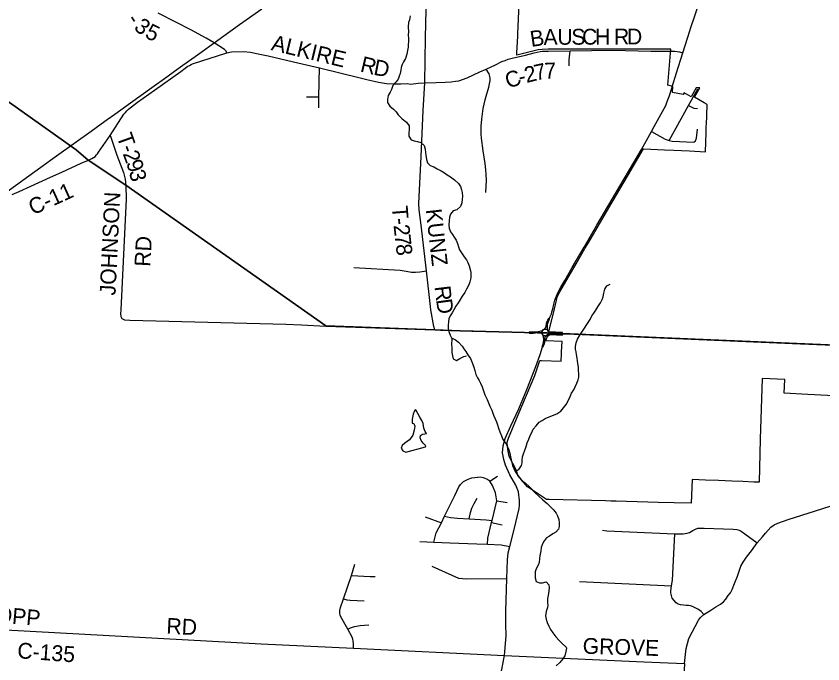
# Model space of a CAD drawing. Extents: x 114604 to 551442, y 316898 to 567001.
# Drawn here: x 152694 to 167961, y 354850 to 367117 of the extents above; entities that cross this region are included whole.
import ezdxf

# ---------------------------------------------------------------- set-up
doc = ezdxf.new("R2010")
doc.units = 0
for name, color, linetype in [('GE_P_Alignment_1000_Bearings', 7, 'Continuous'), ('GE_P_Alignment_1000_Cardinal_Points', 7, 'Continuous'), ('GE_P_Alignment_100_Stations', 7, 'Continuous'), ('GE_P_Alignment_500_Bearings', 7, 'Continuous'), ('GE_P_Alignment_500_Distances', 7, 'Continuous'), ('MT_X_Edge_Line', 7, 'Continuous'), ('PM_P_Cells', 7, 'Continuous'), ('PM_P_CL_Double_Solid', 7, 'Continuous'), ('PM_P_Crosswalk', 7, 'Continuous')]:
    doc.layers.add(name, color=color, linetype=linetype)

msp = doc.modelspace()

# ---------------------------------------------------------------- linework, layer by layer
at = {"layer": 'GE_P_Alignment_1000_Bearings'}
msp.add_lwpolyline([(152238, 363592), (152931, 364091), (153164, 364258), (153458, 364468), (154115, 364941), (154304, 365077), (154417, 365157), (154560, 365260), (154858, 365474), (155261, 365764), (155545, 365968), (155690, 366072), (155851, 366188), (156081, 366353), (156217, 366450), (156352, 366546), (156441, 366612), (156924, 366959), (157342, 367257)], dxfattribs=at)
at = {"layer": 'GE_P_Alignment_1000_Cardinal_Points'}
for p, q in [((163160, 366178), (163161, 366271)), ((158188, 365591), (158422, 365588)), ((160617, 361174), (160725, 361170)), ((161317, 361151), (162394, 361123)), ((163004, 361103), (163057, 361101)), ((163057, 361101), (163110, 361098)), ((163110, 361098), (167387, 360918)), ((161658, 358308), (161802, 358406)), ((161792, 357935), (161985, 357904)), ((160433, 357638), (160743, 357522)), ((161691, 357527), (161890, 357483)), ((163358, 356409), (165099, 356328))]:
    msp.add_line(p, q, dxfattribs=at)
for points in [[(163161, 366271), (163161, 366290), (163180, 366460)], [(158424, 365378), (158422, 365588), (158436, 366135)], [(161590, 365599), (161638, 365772), (161665, 365898), (161666, 365949), (161643, 366023), (161588, 366115)], [(160617, 361174), (160596, 361238), (160543, 361555), (160535, 361619), (160457, 362293), (160361, 363160), (160324, 363451), (160318, 363567), (160359, 364461), (160400, 365332), (160431, 365854)], [(165050, 364762), (165420, 365427), (165594, 365741)], [(161584, 363777), (161594, 364008), (161590, 364118), (161582, 364208), (161571, 364327), (161534, 364564), (161501, 364806), (161496, 364881), (161492, 365036), (161505, 365168), (161530, 365365), (161571, 365531), (161590, 365599)], [(165420, 365427), (165521, 365374), (165592, 365368)], [(164719, 364933), (164979, 364787), (165050, 364762), (165110, 364750), (165517, 364729), (165553, 364757), (165572, 364807), (165586, 364976)], [(154474, 364859), (154489, 364827), (154602, 364486), (154724, 364154), (154755, 364030), (154770, 363911)], [(154770, 363911), (154778, 363650), (154673, 361553), (154669, 361481), (154673, 361427), (154697, 361391), (154745, 361367), (154847, 361357), (157801, 361281), (158095, 361268)], [(159085, 362354), (159959, 362309), (160073, 362288), (160177, 362269), (160251, 362266), (160331, 362277), (160457, 362293)], [(158095, 361268), (158557, 361248), (160617, 361174)], [(160725, 361170), (161096, 361157), (161317, 361151)], [(162394, 361123), (162411, 361136), (162438, 361136), (162476, 361138), (162529, 361141), (162573, 361144), (162608, 361149), (162633, 361157), (162650, 361165), (162674, 361180)], [(162394, 361123), (162410, 361112), (162440, 361112), (162478, 361115), (162525, 361120), (162574, 361125), (162601, 361125), (162624, 361117), (162642, 361106), (162649, 361099)], [(162649, 361099), (162659, 361086), (162671, 361077), (162683, 361071), (162695, 361067), (162708, 361065), (162720, 361068), (162734, 361075)], [(162674, 361180), (162687, 361186), (162700, 361190), (162714, 361190), (162731, 361186), (162747, 361177), (162753, 361171), (162759, 361161)], [(162734, 361075), (162755, 361083), (162777, 361091), (162809, 361097), (162843, 361099), (162877, 361098), (162984, 361093), (163004, 361103)], [(162759, 361161), (162770, 361147), (162781, 361135), (162794, 361127), (162809, 361121), (162826, 361119), (162862, 361118), (162940, 361117), (162968, 361115), (162986, 361113), (163004, 361103)], [(167387, 360918), (169394, 360833), (170478, 360795)], [(160602, 357152), (160630, 357282), (160646, 357332), (160743, 357522), (160802, 357648), (160999, 358038), (161074, 358204), (161104, 358246), (161162, 358303), (161250, 358347), (161318, 358375), (161430, 358389)], [(161612, 357116), (161620, 357230), (161691, 357527), (161705, 357565), (161792, 357935), (161768, 358090), (161710, 358228), (161658, 358308), (161602, 358348), (161538, 358374), (161506, 358380), (161430, 358389)], [(161265, 357594), (161291, 357720), (161319, 357802), (161363, 357887), (161417, 357987)], [(160802, 357648), (160913, 357623), (161045, 357607), (161265, 357594), (161589, 357577), (161705, 357565)], [(163791, 357381), (163873, 357371), (165163, 357313), (165315, 357311), (165396, 357323), (165437, 357339), (165498, 357376), (165549, 357404), (165597, 357418), (165646, 357423), (165717, 357422), (166267, 357400), (166331, 357393), (166375, 357382), (166416, 357364), (166486, 357315), (166718, 357144)], [(165707, 355785), (165657, 355839), (165606, 355878), (165497, 355935), (165459, 355950), (165421, 355955), (165375, 355957), (165321, 355959), (165270, 355966), (165225, 355981), (165185, 356007), (165145, 356049), (165112, 356096), (165095, 356145), (165085, 356193), (165086, 356236), (165099, 356328), (165113, 356433), (165163, 357313)], [(160334, 357167), (160602, 357152), (160904, 357142), (161414, 357122), (161612, 357116), (161872, 357105), (162036, 357070)], [(159078, 355148), (159079, 355238), (159073, 355282), (159064, 355321), (159052, 355353), (158973, 355507), (158839, 355741), (158829, 355770), (158823, 355810), (158823, 355861), (158830, 355916), (158888, 356083), (159038, 356524), (159103, 356737)], [(160559, 356701), (161065, 356474), (161219, 356461), (161979, 356467)], [(159038, 356524), (159394, 356505), (159491, 356504)], [(158888, 356083), (158954, 356065), (159018, 356057), (159282, 356047)], [(158973, 355507), (159024, 355532), (159099, 355560), (159207, 355576), (159367, 355587)]]:
    msp.add_lwpolyline(points, dxfattribs=at)
at = {"layer": 'GE_P_Alignment_100_Stations'}
msp.add_lwpolyline([(168540, 359910), (167678, 359953), (167227, 359975), (167239, 360236), (166810, 360257), (166777, 359104), (166754, 358290), (166655, 358294), (166448, 358302), (166239, 358310), (165989, 358320), (165740, 358330), (165490, 358340), (165469, 357891), (165149, 357900), (164847, 357908), (164647, 357914), (164447, 357919), (164248, 357925), (164048, 357930), (163951, 357932), (163847, 357935), (162780, 357963), (162731, 357964), (162374, 358204), (162295, 358293), (162186, 358418), (162163, 358511), (162024, 358779), (162002, 358919), (161984, 359031), (161992, 359069), (162011, 359127), (162198, 359569), (162508, 360309), (162606, 360595), (162637, 360594), (163010, 360582), (163011, 360612), (163014, 360687), (163017, 360762), (163025, 360955), (162719, 360967), (162751, 361058), (162807, 361085), (163031, 361075), (163031, 361075), (163031, 361086), (163034, 361126), (162774, 361136), (162880, 361576), (162920, 361740), (162936, 361794), (162956, 361846), (162981, 361897), (163290, 362425), (163459, 362715), (163532, 362839), (163911, 363489), (164264, 364086), (164564, 364603), (164575, 364602), (164964, 364585), (165138, 364577), (165289, 364570), (165438, 364563), (165639, 364554), (165741, 364549), (165747, 364729), (165753, 364905), (165756, 364987), (165761, 365118), (165763, 365187), (165765, 365235), (165773, 365445), (165718, 365476), (165531, 365582), (165632, 365760), (165562, 365761), (165466, 365588), (165335, 365662), (165319, 365633), (165114, 365673), (165124, 365784), (165025, 365812), (165087, 366491), (164992, 366494), (163890, 366493), (162763, 366494), (162646, 366486), (162576, 366476), (162171, 366378), (162179, 366571), (162180, 366588), (162188, 366780), (162230, 367784)], dxfattribs=at)
at = {"layer": 'GE_P_Alignment_500_Bearings'}
msp.add_line((165345, 354855), (165285, 353903), dxfattribs=at)
for points in [[(160431, 365854), (160440, 366710), (160471, 368026), (160485, 368388), (160489, 368477), (160495, 368532), (161383, 368509), (162233, 368476), (162646, 368457), (163006, 368450), (163461, 368434), (163968, 368418), (164072, 368411), (164726, 368389), (164923, 368382)], [(165472, 366920), (165531, 367102), (165640, 367430), (165714, 367677), (165746, 367821), (165765, 367984), (165766, 368101), (165764, 368348)], [(156684, 366423), (156669, 366453), (156634, 366483), (156441, 366609), (156289, 366702), (156000, 366860), (155731, 366994), (155380, 367170)], [(165104, 365755), (165111, 365780), (165193, 366042), (165313, 366420), (165408, 366718), (165472, 366920)], [(156684, 366423), (156769, 366442), (156995, 366444), (157131, 366435), (157272, 366405), (157464, 366363), (157942, 366250), (158436, 366135), (159203, 365947), (159334, 365914), (159550, 365867), (159704, 365842), (159835, 365833), (159974, 365836), (160095, 365843), (160166, 365827), (160300, 365846), (160431, 365854)], [(160431, 365854), (160641, 365857), (160815, 365866), (160928, 365872), (161006, 365883), (161071, 365894), (161228, 365948), (161469, 366061), (161588, 366115), (161764, 366197), (161886, 366255), (161951, 366278), (162007, 366300), (162083, 366320), (162332, 366380), (162497, 366421), (162609, 366445), (162646, 366451), (162695, 366454), (162768, 366455), (163180, 366460), (163986, 366470), (164704, 366455), (165084, 366454), (165156, 366456), (165161, 366455)], [(165161, 366455), (165207, 366449), (165251, 366439), (165313, 366420)], [(154474, 364859), (154735, 365257), (154765, 365294), (154791, 365326), (154820, 365355), (154993, 365486), (155314, 365716), (155810, 366071), (155894, 366133), (155943, 366166), (155976, 366184), (156005, 366199), (156034, 366211), (156684, 366423)], [(164771, 365027), (164990, 365426), (165017, 365501), (165055, 365593), (165104, 365755)], [(162850, 361571), (162872, 361662), (162890, 361737), (162933, 361843), (162964, 361914), (163003, 361986), (163075, 362112), (163220, 362359), (163444, 362743), (163686, 363155), (164120, 363896), (164529, 364592), (164719, 364933), (164771, 365027)], [(154160, 364437), (154164, 364440), (154189, 364460), (154215, 364487), (154233, 364508), (154255, 364538), (154474, 364859)], [(152619, 363737), (152753, 363798), (152969, 363897), (153346, 364069), (153556, 364164), (153927, 364330), (154061, 364387), (154129, 364418), (154160, 364437)], [(162786, 361399), (162800, 361430), (162812, 361456), (162823, 361482), (162835, 361515), (162850, 361571)], [(162674, 361180), (162695, 361198), (162712, 361216), (162724, 361236), (162727, 361255), (162730, 361278), (162734, 361300), (162739, 361319), (162748, 361341), (162757, 361360), (162773, 361389), (162786, 361399)], [(162759, 361161), (162752, 361187), (162750, 361209), (162751, 361235), (162753, 361272), (162759, 361298), (162770, 361336), (162781, 361363), (162791, 361382), (162786, 361399)], [(162649, 361099), (162647, 361113), (162647, 361126), (162649, 361138), (162654, 361154), (162659, 361166), (162674, 361180)], [(162657, 360853), (162652, 360865), (162661, 360891), (162672, 360928), (162677, 360955), (162680, 360982), (162678, 361009), (162676, 361032), (162672, 361053), (162664, 361073), (162649, 361099)], [(162734, 361075), (162750, 361086), (162760, 361097), (162765, 361113)], [(162765, 361113), (162767, 361131), (162765, 361145), (162759, 361161)], [(162657, 360853), (162673, 360863), (162682, 360885), (162692, 360911), (162697, 360938), (162702, 360968), (162704, 360998), (162703, 361021), (162706, 361040), (162714, 361054), (162722, 361065), (162734, 361075)], [(161963, 355612), (161960, 355849), (161979, 356467), (161990, 356823), (162006, 356953), (162036, 357070), (162120, 357394), (162214, 357791), (162218, 357856), (162222, 357944), (162199, 358106), (162153, 358232), (162039, 358428), (161954, 358615), (161924, 358721), (161900, 358849), (161912, 358979), (161952, 359118), (162058, 359358), (162208, 359683), (162359, 360048), (162529, 360480), (162610, 360708), (162657, 360853)], [(165345, 354855), (165374, 355142), (165427, 355330), (165605, 355678), (165643, 355727), (165707, 355785), (165839, 355867), (165937, 355929), (166025, 355984), (166079, 356025), (166127, 356076), (166171, 356142), (166211, 356195), (166243, 356261), (166288, 356371), (166343, 356510), (166376, 356609), (166411, 356699), (166455, 356778), (166519, 356868), (166608, 356993), (166718, 357144), (166816, 357259), (166878, 357326), (166977, 357437), (167039, 357481), (167109, 357517), (167303, 357582), (168476, 357954)], [(161939, 355007), (161966, 355382), (161963, 355597), (161963, 355612)], [(151703, 355576), (151739, 355560), (151791, 355541), (152044, 355517), (152497, 355497), (157329, 355232), (159078, 355148), (161939, 355007)], [(160403, 351997), (160487, 352071), (160621, 352165), (160745, 352275), (160859, 352435), (160968, 352619), (161100, 352900), (161324, 353358), (161506, 353819), (161706, 354289), (161856, 354646), (161884, 354744), (161907, 354845), (161939, 355007)], [(161939, 355007), (164576, 354891), (165345, 354855)]]:
    msp.add_lwpolyline(points, dxfattribs=at)
at = {"layer": 'GE_P_Alignment_500_Distances'}
for points in [[(146990, 369445), (153829, 364582), (154060, 364390), (154769, 363914), (158556, 361251), (160616, 361177), (161095, 361159), (162560, 361122), (162739, 361117), (169393, 360836), (170477, 360798), (172520, 360708), (172368, 357901), (172150, 354165)], [(169393, 360836), (162739, 361117), (162560, 361122), (161095, 361159), (160616, 361177), (158556, 361251), (154769, 363914), (154060, 364390), (153829, 364582), (146990, 369445)]]:
    msp.add_lwpolyline(points, dxfattribs=at)
at = {"layer": 'MT_X_Edge_Line'}
for points in [[(160440, 358958), (160446, 358978), (160396, 359032), (160356, 359080), (160342, 359134), (160349, 359178), (160385, 359202), (160431, 359204), (160459, 359216), (160435, 359252), (160409, 359314), (160400, 359405), (160372, 359461), (160334, 359521), (160296, 359589), (160265, 359647), (160247, 359659), (160229, 359631), (160206, 359578), (160190, 359487), (160186, 359443), (160188, 359407), (160220, 359401), (160237, 359349), (160229, 359279), (160203, 359181), (160138, 359095), (160052, 359033), (160000, 358987), (159983, 358935), (160015, 358887), (160071, 358861)], [(160071, 358861), (160440, 358958)]]:
    msp.add_lwpolyline(points, dxfattribs=at)
at = {"layer": 'PM_P_Cells'}
for points in [[(160152, 367124), (160138, 367046), (160121, 366994), (160113, 366912), (160117, 366818), (160116, 366760), (160118, 366684), (160118, 366628), (160115, 366578), (160111, 366526), (160103, 366466), (160089, 366394), (160060, 366312), (160024, 366252), (159998, 366200), (159981, 366144), (159975, 366094), (159959, 366032), (159941, 365978), (159924, 365926), (159888, 365872), (159826, 365800), (159796, 365730), (159775, 365676), (159737, 365614), (159719, 365536), (159724, 365480), (159766, 365411), (159836, 365357), (159888, 365305), (159927, 365245), (159997, 365170), (160079, 365108), (160131, 365042), (160130, 364969), (160126, 364907)], [(160126, 364907), (160126, 364843), (160173, 364771), (160229, 364755), (160289, 364742), (160351, 364722), (160413, 364666), (160433, 364598), (160438, 364536), (160446, 364483), (160460, 364401), (160476, 364339), (160529, 364291), (160599, 364263), (160665, 364228), (160735, 364190), (160799, 364148), (160851, 364111), (160914, 364071), (160992, 364017), (161066, 363950), (161102, 363888), (161123, 363826), (161133, 363774), (161139, 363698), (161137, 363648), (161126, 363580), (161104, 363512), (161036, 363450), (160962, 363428), (160915, 363364), (160897, 363308), (160889, 363240), (160884, 363160), (160888, 363102), (160916, 363030), (160952, 362979), (160985, 362929), (161019, 362875), (161047, 362809), (161065, 362745), (161082, 362693), (161132, 362616), (161174, 362556), (161214, 362500), (161241, 362448), (161265, 362391), (161287, 362321), (161296, 362263), (161300, 362213), (161296, 362159), (161280, 362087), (161261, 362027), (161215, 361949), (161183, 361883), (161138, 361813), (161094, 361739), (161058, 361685), (161014, 361623), (160975, 361553), (160945, 361499), (160909, 361439), (160884, 361383), (160874, 361329), (160872, 361263), (160872, 361195), (160881, 361145), (160909, 361077), (160933, 361027), (161009, 360986), (161065, 360944), (161134, 360868), (161166, 360818), (161204, 360767), (161240, 360705), (161295, 360631), (161333, 360537), (161354, 360466), (161372, 360404), (161396, 360330), (161428, 360270), (161457, 360216), (161481, 360163), (161511, 360097), (161533, 360041), (161564, 359947), (161606, 359859), (161636, 359796), (161659, 359728), (161695, 359654), (161731, 359562), (161760, 359491), (161782, 359433), (161802, 359379), (161825, 359311), (161847, 359245), (161877, 359171), (161907, 359100), (161970, 359018), (161996, 358962), (162020, 358902)], [(162138, 358491), (162206, 358534), (162260, 358608), (162269, 358660), (162273, 358710), (162279, 358770), (162297, 358827), (162316, 358879), (162346, 358965), (162364, 359037), (162397, 359105), (162425, 359174), (162455, 359232), (162480, 359296), (162534, 359358), (162594, 359428), (162646, 359460), (162706, 359496), (162783, 359530), (162927, 359585), (163005, 359639), (163055, 359701), (163102, 359763), (163142, 359831), (163176, 359915), (163203, 359977), (163247, 360039), (163271, 360097), (163308, 360169), (163330, 360227), (163342, 360279), (163346, 360337), (163339, 360415), (163337, 360469), (163327, 360541), (163317, 360591), (163310, 360641), (163296, 360709), (163292, 360759), (163282, 360812), (163283, 360862), (163293, 360928), (163317, 361000), (163364, 361076), (163398, 361130), (163436, 361187), (163509, 361299), (163559, 361373), (163591, 361439), (163626, 361491), (163662, 361547), (163702, 361609), (163752, 361689), (163783, 361751), (163801, 361803), (163815, 361871), (163832, 361945), (163872, 362007), (163936, 362043)], [(160933, 361027), (160937, 361001), (160936, 360897), (160938, 360834), (160942, 360748), (160949, 360686), (160963, 360624), (161025, 360598), (161093, 360634), (161165, 360673), (161215, 360681)], [(162020, 358902), (162035, 358842), (162051, 358771), (162063, 358715), (162073, 358661), (162086, 358609), (162110, 358553), (162138, 358491), (162174, 358434), (162213, 358384), (162259, 358330), (162335, 358270), (162403, 358207), (162518, 358091), (162586, 358024), (162660, 357958), (162741, 357890), (162811, 357821), (162863, 357769), (162911, 357707), (162940, 357652), (162962, 357586), (162972, 357520), (162971, 357452), (162961, 357400), (162909, 357342), (162851, 357310), (162785, 357266), (162728, 357235), (162676, 357163), (162648, 357105), (162632, 357053), (162621, 356991), (162605, 356899), (162599, 356847), (162592, 356773), (162576, 356721), (162536, 356647), (162519, 356591), (162517, 356534), (162517, 356482), (162533, 356412), (162599, 356386), (162653, 356388), (162725, 356402), (162776, 356349), (162784, 356297), (162776, 356225), (162762, 356147), (162753, 356089), (162753, 356009), (162755, 355953), (162746, 355897), (162726, 355845), (162710, 355759), (162724, 355695), (162745, 355632), (162775, 355562), (162807, 355504), (162852, 355440), (162908, 355363), (162974, 355293), (163028, 355237), (163103, 355168)], [(163103, 355168), (163110, 355145), (163099, 355083), (163075, 355005), (163038, 354943), (162982, 354874), (162915, 354816)]]:
    msp.add_lwpolyline(points, dxfattribs=at)

# ---------------------------------------------------------------- texts
at = {"layer": 'PM_P_CL_Double_Solid'}
for s, rotation, p in [('-', 304.2729, (154774, 367048)), ('3', 320.4981, (154906, 366878)), ('5', 334.1524, (155114, 366719)), ('ALKIRE', 346.422, (157505, 366476)), ('B', 8.2941, (162442, 366533)), ('A', 1.3304, (162676, 366568)), ('U', 0.2958, (162938, 366574)), ('S', 0.2746, (163202, 366575)), ('C', 0.2719, (163405, 366576)), ('H', 0.2704, (163651, 366578)), ('R', 0.2719, (164008, 366579)), ('D', 0.2704, (164254, 366580)), ('R', 346.5228, (159190, 366070)), ('D', 349.1468, (159444, 366009)), ('2', 13.9324, (162352, 365849)), ('7', 12.3214, (162530, 365893)), ('7', 2.4164, (162697, 365931)), ('C', 18.8214, (162006, 365741)), ('-', 14.0927, (162233, 365819)), ('C-11', 24.3749, (153012, 363343)), ('KROPP', 355.1012, (151742, 355686)), ('RD', 356.959, (155531, 355423)), ('GROVE', 358.2168, (163412, 355044)), ('C-135', 355.7177, (152708, 354959))]:
    msp.add_text(s, height=300, rotation=rotation, dxfattribs=at).set_placement(p)
at = {"layer": 'PM_P_Crosswalk'}
for s, rotation, p in [('T', 289.6755, (154591, 364841)), ('-', 289.8544, (154666, 364629)), ('2', 290.0232, (154708, 364513)), ('9', 289.0862, (154771, 364342)), ('3', 282.6514, (154828, 364177)), ('JOHNSON', 87.2491, (154573, 361822)), ('T', 274.3453, (159803, 363515)), ('KUNZ', 276.37, (160446, 363454)), ('-', 276.1291, (159821, 363282)), ('2', 276.4344, (159835, 363157)), ('RD', 86.9589, (155232, 362366)), ('7', 276.5489, (159855, 362973)), ('8', 276.5863, (159877, 362789)), ('R', 276.9051, (160611, 361995)), ('D', 277.7492, (160641, 361746))]:
    msp.add_text(s, height=300, rotation=rotation, dxfattribs=at).set_placement(p)

doc.saveas('drawing.dxf')
